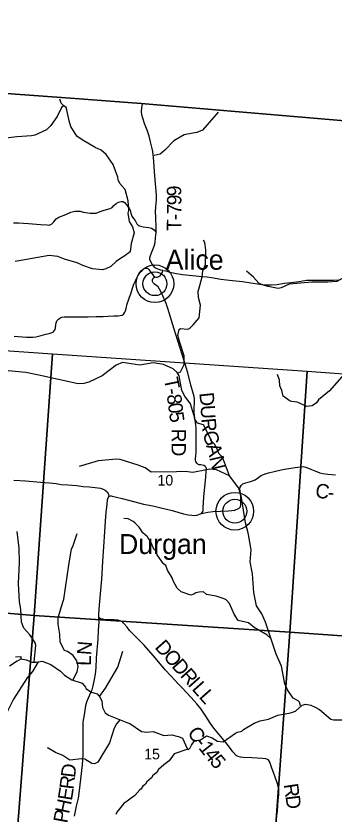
# Model space of a CAD drawing. Extents: x 1878108 to 2183446, y 146837 to 508383.
# Drawn here: x 2001746 to 2008379, y 360858 to 377520 of the extents above; entities that cross this region are included whole.
import ezdxf

# ---------------------------------------------------------------- set-up
doc = ezdxf.new("R2010")
doc.units = 0
for name, color, linetype in [('GM_X_Adjacent_County', 7, 'Continuous'), ('GM_X_County', 7, 'Continuous'), ('GM_X_County_Road', 7, 'Continuous'), ('GM_X_County_Road_Text', 7, 'Continuous'), ('GM_X_Minor_River', 7, 'Continuous'), ('GM_X_Section', 7, 'Continuous'), ('GM_X_Section_Text', 7, 'Continuous'), ('GM_X_Township', 7, 'Continuous'), ('GM_X_Township_Road', 7, 'Continuous'), ('GM_X_Township_Road_Text', 7, 'Continuous'), ('GM_X_Unincorporated', 7, 'Continuous'), ('GM_X_Unincorporated_Location', 7, 'Continuous'), ('GM_X_Unincorporated_Text', 7, 'Continuous')]:
    doc.layers.add(name, color=color, linetype=linetype)

msp = doc.modelspace()

# ---------------------------------------------------------------- linework, layer by layer
at = {"layer": 'GM_X_Adjacent_County'}
msp.add_lwpolyline([(2019246, 379371), (2019091, 377354), (2019015, 375973), (2018932, 374460), (2017235, 374591), (2014948, 374808), (2013541, 374918), (2012706, 374993), (2009261, 375273), (2004355, 375690), (2002882, 375803), (1999924, 376023), (1996643, 376255), (1995226, 376368), (1992658, 376556), (1989295, 376815), (1988220, 376891), (1986880, 376990), (1987114, 379254)], dxfattribs=at)
at = {"layer": 'GM_X_County'}
msp.add_lwpolyline([(1999924, 376023), (2002882, 375803), (2004355, 375690), (2009261, 375273), (2012706, 374993), (2013541, 374918), (2014948, 374808), (2017235, 374591), (2018932, 374460), (2018869, 373505), (2018611, 369652), (2018544, 369044), (2019394, 369075)], dxfattribs=at)
at = {"layer": 'GM_X_County_Road'}
for points in [[(2003832, 371261), (2003874, 371262), (2003918, 371265), (2003962, 371277), (2003992, 371304), (2004014, 371333), (2004028, 371364), (2004044, 371415), (2004068, 371512), (2004094, 371587), (2004114, 371650), (2004138, 371720), (2004175, 371834), (2004207, 371921), (2004243, 372007), (2004272, 372066), (2004290, 372097), (2004312, 372134), (2004337, 372171), (2004368, 372202), (2004396, 372230), (2004416, 372246), (2004440, 372256), (2004463, 372257), (2004484, 372253), (2004498, 372245), (2004515, 372227), (2004528, 372204), (2004551, 372179), (2004585, 372134), (2004614, 372098), (2004641, 372074), (2004672, 372065), (2004697, 372068), (2004724, 372078), (2004751, 372098), (2004802, 372170), (2004812, 372206), (2004869, 372196), (2004956, 372170), (2005091, 372143), (2005218, 372126), (2005430, 372099), (2005629, 372078), (2005735, 372071), (2005824, 372059), (2006017, 372028), (2006137, 372008), (2006259, 371995), (2006470, 371975), (2006642, 371952), (2006830, 371923), (2006955, 371910), (2007067, 371909), (2007193, 371917), (2007337, 371940), (2007476, 371958), (2007651, 371980), (2007802, 372001), (2007885, 372006), (2008006, 372006), (2008200, 372006), (2008362, 372007), (2008465, 372013)], [(2001710, 370832), (2001963, 370814), (2002097, 370812), (2002162, 370821), (2002268, 370848), (2002368, 370876), (2002438, 370890), (2002482, 370902), (2002519, 370922), (2002545, 370946), (2002561, 370976), (2002570, 371008), (2002575, 371075), (2002581, 371115), (2002599, 371154), (2002631, 371193), (2002672, 371219), (2002701, 371230), (2002753, 371238), (2002863, 371240), (2003005, 371240), (2003253, 371240), (2003419, 371245), (2003567, 371249), (2003671, 371254), (2003787, 371260), (2003832, 371261)], [(2003679, 367483), (2003693, 367496), (2003713, 367500), (2003734, 367501), (2003754, 367496), (2003845, 367474), (2003959, 367445), (2004222, 367376), (2004407, 367330), (2004598, 367293), (2004711, 367267), (2005001, 367198), (2005122, 367159), (2005240, 367126), (2005335, 367104), (2005415, 367095), (2005467, 367092), (2005518, 367100), (2005616, 367130), (2005749, 367164), (2005850, 367175), (2006013, 367182), (2006177, 367187), (2006247, 367197), (2006300, 367204), (2006361, 367220), (2006402, 367243), (2006426, 367275), (2006436, 367318), (2006435, 367395), (2006437, 367479), (2006430, 367542), (2006419, 367606), (2006416, 367643), (2006421, 367684), (2006440, 367719), (2006478, 367752), (2006537, 367775), (2006638, 367801), (2006682, 367813), (2006735, 367837), (2006812, 367892), (2006860, 367923), (2006945, 367963), (2007013, 367985), (2007130, 368009), (2007278, 368045), (2007344, 368060), (2007569, 368096), (2007682, 368110), (2007736, 368111), (2007793, 368100), (2007907, 368054), (2007979, 368023), (2008033, 368002), (2008081, 367981), (2008147, 367967), (2008251, 367955), (2008407, 367943)], [(2002964, 360813), (2003010, 361023), (2003047, 361189), (2003069, 361348), (2003100, 361587), (2003130, 361883), (2003147, 362092), (2003148, 362221), (2003147, 362411), (2003146, 362572), (2003150, 362778), (2003172, 362931), (2003201, 363124), (2003223, 363201), (2003256, 363282), (2003309, 363395), (2003332, 363452), (2003357, 363537), (2003386, 363668), (2003406, 363775), (2003418, 363908), (2003426, 364120), (2003457, 364510), (2003466, 364687), (2003479, 364871), (2003477, 364961), (2003473, 365032), (2003480, 365135), (2003511, 365453), (2003535, 365764), (2003560, 366131), (2003581, 366436), (2003597, 366754), (2003615, 366973), (2003630, 367156), (2003645, 367331), (2003656, 367420), (2003666, 367463), (2003679, 367483)], [(2003982, 364853), (2003966, 364869), (2003922, 364891), (2003871, 364905), (2003792, 364910), (2003682, 364911), (2003606, 364916), (2003550, 364925), (2003508, 364937), (2003477, 364961)], [(2007190, 360851), (2007205, 361022), (2007216, 361148), (2007225, 361259), (2007229, 361354), (2007224, 361404), (2007207, 361469), (2007139, 361667), (2007083, 361817), (2007040, 361938), (2007020, 361977), (2006993, 361999), (2006957, 362010), (2006888, 362018), (2006667, 362030), (2006486, 362038), (2006429, 362043), (2006379, 362059), (2006341, 362078), (2006272, 362155), (2006221, 362230), (2006126, 362352), (2005976, 362529), (2005874, 362652), (2005802, 362746), (2005706, 362900), (2005664, 362965), (2005606, 363051), (2005517, 363156), (2005398, 363290), (2005287, 363411), (2005223, 363476), (2005129, 363578), (2004976, 363747), (2004858, 363872), (2004659, 364114), (2004420, 364381), (2004311, 364494), (2004237, 364564), (2004152, 364650), (2004113, 364692), (2004063, 364758), (2004005, 364830), (2003982, 364853)]]:
    msp.add_lwpolyline(points, dxfattribs=at)
at = {"layer": 'GM_X_Minor_River'}
for points in [[(2002745, 375646), (2002687, 375699), (2002658, 375784)], [(2004015, 373906), (2003912, 374026), (2003876, 374096), (2003870, 374152), (2003774, 374418), (2003630, 374630), (2003520, 374718), (2003400, 374776), (2003124, 374932), (2003012, 375012), (2002892, 375216), (2002852, 375328), (2002807, 375562), (2002793, 375610), (2002745, 375646), (2002694, 375606), (2002608, 375424), (2002470, 375231), (2002382, 375143), (2002137, 375030), (2002073, 375016), (2001761, 374998), (2001250, 374931)], [(2005964, 375512), (2005635, 375137), (2005517, 375087), (2005437, 375074), (2005253, 375038), (2005040, 374915), (2004850, 374721), (2004750, 374635), (2004625, 374604)], [(2004015, 373907), (2004076, 373667), (2004092, 373462), (2004077, 373402), (2004108, 373229), (2004176, 373121), (2004211, 372990), (2004147, 372767), (2004129, 372598), (2003996, 372497)], [(2005117, 370065), (2005177, 370089), (2005251, 370245), (2005251, 370422), (2005165, 370700), (2005124, 370850), (2005148, 370976), (2005176, 370994), (2005320, 370980), (2005364, 370997), (2005444, 371075), (2005566, 371215), (2005595, 371480), (2005551, 371644), (2005549, 371774), (2005561, 371818), (2005630, 372075), (2005646, 372201), (2005696, 372333), (2005704, 372641), (2005686, 372788), (2005658, 372842)], [(2003997, 372497), (2003966, 372486), (2003832, 372396), (2003722, 372289), (2003618, 372239), (2003548, 372219), (2003341, 372239), (2003139, 372310), (2003021, 372368), (2002761, 372442), (2002621, 372498), (2002439, 372517), (2002204, 372481), (2001730, 372392)], [(2009454, 372110), (2009273, 372117), (2009093, 372079), (2008849, 372112), (2008729, 372124), (2008643, 372094), (2008436, 371978), (2008248, 371965), (2007916, 371963), (2007441, 371924), (2007279, 371847), (2007215, 371833), (2007003, 371869), (2006881, 371909), (2006809, 371945), (2006699, 372064), (2006551, 372190)], [(2009264, 370889), (2009168, 370627), (2009138, 370549), (2009043, 370450), (2008969, 370424), (2008899, 370430), (2008851, 370360), (2008775, 370304), (2008741, 370218), (2008288, 369692), (2008057, 369507), (2008011, 369445), (2007925, 369379), (2007811, 369367), (2007609, 369456), (2007499, 369468), (2007465, 369480), (2007320, 369580), (2007289, 369704), (2007247, 369798), (2007241, 369918), (2007201, 370035)], [(2003966, 370287), (2003832, 370233), (2003543, 370006), (2003263, 369875), (2003164, 369849), (2003046, 369843), (2002220, 370021), (2001953, 370079), (2001583, 370112)], [(2007681, 363116), (2007658, 363192), (2007634, 363220), (2007527, 363274), (2007410, 363450), (2007356, 363578), (2007286, 363946), (2007174, 364196), (2006947, 364861), (2006873, 365035), (2006763, 365203), (2006707, 365485), (2006676, 365876), (2006630, 366124), (2006654, 366372), (2006596, 366693), (2006584, 366757), (2006531, 366939), (2006447, 367470), (2006391, 367660), (2006201, 367922), (2006050, 368306), (2005976, 368384), (2005952, 368468), (2005886, 368582), (2005818, 368650), (2005790, 368726), (2005654, 368982), (2005532, 369016), (2005478, 369100), (2005462, 369180), (2005446, 369212), (2005386, 369422), (2005266, 369584), (2005208, 369704), (2005151, 370007), (2005109, 370079), (2005025, 370155), (2004825, 370246), (2004608, 370278), (2004332, 370232), (2003966, 370287)], [(2003917, 368262), (2003841, 368268), (2003459, 368233), (2003064, 368112)], [(2006201, 367922), (2005931, 368043), (2005787, 368057), (2005719, 368045), (2005437, 367990), (2005275, 368008), (2005094, 368006), (2004566, 367993), (2004440, 368089), (2004292, 368145), (2003917, 368262), (2003917, 368254)], [(2007065, 364517), (2006976, 364598), (2006714, 364750), (2006594, 364852), (2006382, 364900), (2006294, 365028), (2006202, 365254), (2006132, 365328), (2006086, 365348), (2005922, 365410), (2005720, 365441), (2005658, 365499), (2005564, 365487), (2005500, 365479), (2005456, 365447), (2005394, 365431), (2005194, 365494), (2005110, 365572), (2005024, 365728), (2005000, 365791), (2004906, 365953), (2004870, 366049), (2004824, 366079), (2004690, 366269), (2004656, 366361), (2004622, 366389), (2004554, 366553), (2004522, 366583), (2004492, 366647), (2004390, 366729), (2004312, 366845), (2004224, 366937), (2004192, 366963), (2004086, 367021), (2003992, 367030)], [(2002125, 364029), (2002159, 364383), (2002143, 364431), (2002111, 364487), (2002037, 364597), (2001907, 364741), (2001861, 364863), (2001848, 365134), (2001822, 365290), (2001796, 365669), (2001819, 366107), (2001811, 366418), (2001807, 366464), (2001773, 366760)], [(2002758, 364272), (2002669, 364448), (2002663, 364615), (2002624, 364823), (2002626, 364954), (2002687, 365171), (2002741, 365343), (2002845, 366057), (2002904, 366393), (2002931, 366445), (2003025, 366718)], [(2002932, 363651), (2003022, 363827), (2003045, 363939), (2003014, 364054), (2002939, 364165), (2002823, 364250), (2002758, 364272)], [(2003488, 363311), (2003613, 363489), (2003870, 363922), (2003969, 364238), (2003977, 364262)], [(2001739, 364142), (2001849, 364145), (2001847, 364095), (2001774, 364048), (2001611, 363945)], [(2001847, 364097), (2001961, 364079), (2002083, 364029), (2002165, 364029), (2002293, 364049), (2002473, 363983), (2002675, 363842), (2002757, 363758), (2002909, 363658), (2003129, 363594), (2003193, 363510), (2003203, 363482), (2003323, 363404), (2003437, 363368), (2003503, 363294), (2003537, 363216), (2003551, 363086), (2003605, 362972), (2003675, 362924), (2004059, 362769), (2004117, 362749), (2004361, 362583), (2004477, 362565), (2004604, 362583), (2004828, 362498), (2004998, 362510), (2005104, 362484), (2005132, 362480), (2005216, 362442), (2005316, 362224), (2005342, 362208), (2005380, 362240), (2005410, 362296), (2005468, 362389), (2005594, 362409), (2005721, 362489), (2005841, 362449), (2005891, 362415), (2005947, 362383), (2006069, 362366), (2006327, 362550), (2006369, 362566), (2006454, 362585), (2006490, 362621), (2006716, 362755), (2006838, 362806), (2007012, 362836), (2007207, 362925), (2007469, 362969), (2007577, 363009), (2007713, 363132), (2007794, 363152), (2007898, 363130), (2007988, 363088), (2008074, 363042), (2008310, 362842), (2008370, 362824), (2008570, 362827)], [(2002208, 364036), (2002093, 363835), (2001979, 363701), (2001697, 363258), (2001566, 363004), (2001404, 362757), (2001275, 362487), (2001185, 362342), (2001070, 362200), (2000888, 361993), (2000802, 361871), (2000566, 361649), (2000439, 361573), (2000273, 361545), (2000064, 361542), (1999936, 361545), (1999872, 361552), (1999567, 361683)], [(2003918, 362832), (2003843, 362743), (2003794, 362649), (2003697, 362343), (2003453, 361940), (2003382, 361906), (2003330, 361913), (2003183, 362002), (2003111, 362011), (2002868, 361985), (2002725, 362080), (2002571, 362140), (2002416, 362233), (2002404, 362239)], [(2005332, 362214), (2005048, 362117), (2004939, 361967), (2004833, 361889), (2004719, 361790), (2004683, 361724), (2004599, 361666), (2004570, 361616), (2004472, 361530), (2004446, 361483), (2004390, 361441), (2004358, 361381), (2004330, 361363), (2004224, 361243), (2003985, 361070), (2003851, 360894), (2003825, 360849)]]:
    msp.add_lwpolyline(points, dxfattribs=at)
at = {"layer": 'GM_X_Section'}
for points in [[(1997204, 370837), (2002510, 370465), (2002125, 365006), (1996800, 365454)], [(2002510, 370465), (2007822, 370107), (2007457, 364655), (2002125, 365006)], [(2013129, 369712), (2012803, 364282), (2007457, 364655), (2007822, 370107)], [(1996800, 365454), (2002125, 365006), (2001716, 359747), (1996427, 360078)], [(2002125, 365006), (2007457, 364655), (2007069, 359307), (2001716, 359747)], [(2012803, 364282), (2012417, 358952), (2007069, 359307), (2007457, 364655)]]:
    msp.add_lwpolyline(points, close=True, dxfattribs=at)
at = {"layer": 'GM_X_Township'}
msp.add_lwpolyline([(1999924, 376023), (2002882, 375803), (2004355, 375690), (2009261, 375273), (2012706, 374993), (2013541, 374918), (2014948, 374808), (2017235, 374591), (2018932, 374460), (2018869, 373505), (2018611, 369652), (2018544, 369044), (2018295, 364714), (2018284, 364566), (2017916, 358581), (2017697, 355615), (2017639, 354834), (2017363, 350985), (2017298, 350114), (2016876, 344501)], dxfattribs=at)
at = {"layer": 'GM_X_Township_Road'}
for points in [[(2004812, 372206), (2004765, 372216), (2004710, 372234), (2004657, 372252), (2004639, 372270), (2004586, 372341), (2004560, 372390), (2004538, 372438), (2004535, 372474), (2004551, 372517), (2004583, 372609), (2004626, 372716), (2004648, 372793), (2004657, 372885), (2004667, 373000), (2004672, 373088), (2004662, 373329), (2004657, 373431), (2004665, 373537), (2004678, 373673), (2004678, 373781), (2004644, 374182), (2004611, 374565), (2004597, 374690), (2004588, 374752), (2004554, 374895), (2004522, 375008), (2004482, 375136), (2004425, 375275), (2004390, 375390), (2004372, 375454), (2004363, 375529), (2004368, 375603), (2004386, 375688)], [(2001691, 373200), (2001797, 373199), (2002008, 373185), (2002260, 373167), (2002398, 373157), (2002440, 373156), (2002486, 373176), (2002532, 373221), (2002586, 373283), (2002640, 373317), (2002786, 373377), (2002893, 373423), (2002970, 373442), (2003040, 373447), (2003084, 373443), (2003150, 373424), (2003292, 373406), (2003354, 373400), (2003416, 373402), (2003501, 373439), (2003561, 373458), (2003633, 373477), (2003710, 373503), (2003749, 373521), (2003790, 373566), (2003833, 373608), (2003882, 373633), (2003939, 373647), (2003980, 373646), (2004010, 373624), (2004060, 373568), (2004106, 373508), (2004128, 373468), (2004141, 373403), (2004160, 373341), (2004197, 373292), (2004229, 373248), (2004267, 373179), (2004302, 373148), (2004341, 373131), (2004399, 373119), (2004462, 373111), (2004514, 373103), (2004574, 373087), (2004626, 373056), (2004667, 373000)], [(2005616, 367130), (2005644, 367175), (2005653, 367198), (2005649, 367249), (2005667, 367481), (2005681, 367610), (2005708, 367896), (2005715, 368012), (2005718, 368073), (2005711, 368096), (2005694, 368117), (2005661, 368134), (2005601, 368147), (2005569, 368152), (2005540, 368164), (2005517, 368184), (2005496, 368218), (2005488, 368243), (2005487, 368277), (2005495, 368334), (2005504, 368406), (2005506, 368489), (2005506, 368657), (2005507, 368827), (2005503, 368920), (2005493, 369035), (2005471, 369171), (2005462, 369256), (2005464, 369331), (2005471, 369448), (2005471, 369511), (2005464, 369574), (2005428, 369691), (2005391, 369809), (2005329, 370071), (2005222, 370432), (2005076, 370891), (2004916, 371410), (2004877, 371514), (2004789, 371725), (2004742, 371819), (2004711, 371863), (2004684, 371885), (2004637, 371921), (2004609, 371951), (2004594, 371977), (2004594, 372011), (2004606, 372043), (2004641, 372074)], [(2001698, 367832), (2001946, 367813), (2002257, 367787), (2002447, 367776), (2002587, 367759), (2002690, 367740), (2002828, 367729), (2003016, 367715), (2003149, 367700), (2003279, 367689), (2003453, 367668), (2003510, 367660), (2003565, 367643), (2003609, 367619), (2003646, 367585), (2003675, 367534), (2003679, 367483)]]:
    msp.add_lwpolyline(points, dxfattribs=at)
at = {"layer": 'GM_X_Unincorporated'}
for centre, radius in [((2004644, 371930), 393), ((2004644, 371930), 249), ((2006310, 367180), 393), ((2006310, 367180), 249)]:
    msp.add_circle(centre, radius, dxfattribs=at)
at = {"layer": 'GM_X_Unincorporated_Location'}
for p, q in [((2004644, 371930), (2004644, 371930)), ((2006310, 367180), (2006310, 367180))]:
    msp.add_line(p, q, dxfattribs=at)

# ---------------------------------------------------------------- texts
at = {"layer": 'GM_X_County_Road_Text'}
for s, rotation, p in [('C', 351.0256, (2007973, 367474)), ('-', 355.484, (2008242, 367432)), ('N', 85.6517, (2003312, 364169)), ('D', 311.6702, (2004627, 364331)), ('O', 311.6702, (2004803, 364134)), ('L', 88.562, (2003306, 363949)), ('D', 311.6702, (2004978, 363937)), ('R', 311.6698, (2005154, 363739)), ('I', 311.6698, (2005318, 363555)), ('L', 311.6693, (2005400, 363463)), ('L', 311.5068, (2005549, 363296)), ('C', 303.8703, (2005309, 362559)), ('-', 308.5791, (2005463, 362333)), ('1', 308.6141, (2005540, 362236)), ('4', 308.685, (2005655, 362091)), ('5', 309.4393, (2005773, 361944)), ('D', 83.2096, (2002977, 361606)), ('R', 83.0847, (2002947, 361361)), ('E', 80.9814, (2002911, 361127)), ('R', 278.5024, (2007328, 361475)), ('D', 277.3179, (2007365, 361233)), ('H', 77.8371, (2002852, 360851)), ('P', 79.6643, (2002816, 360655))]:
    msp.add_text(s, height=300, rotation=rotation, dxfattribs=at).set_placement(p)
at = {"layer": 'GM_X_Section_Text'}
for s, p in [('10', (2004696, 367717)), ('15', (2004419, 362000))]:
    msp.add_text(s, height=221, rotation=0, dxfattribs=at).set_placement(p)
at = {"layer": 'GM_X_Township_Road_Text'}
for s, rotation, p in [('9', 91.8269, (2005195, 373762)), ('9', 90.179, (2005196, 373568)), ('7', 89.5673, (2005194, 373379)), ('T', 89.3271, (2005190, 373030)), ('-', 89.3768, (2005193, 373255)), ('T', 281.8373, (2004826, 369943)), ('8', 277.2922, (2004890, 369608)), ('-', 278.9862, (2004871, 369728)), ('D', 276.0162, (2005568, 369648)), ('0', 277.0747, (2004914, 369425)), ('5', 278.2996, (2004937, 369235)), ('U', 272.9665, (2005595, 369390)), ('R', 275.5487, (2005610, 369112)), ('RD', 270, (2004990, 368905)), ('G', 283.4517, (2005641, 368822)), ('A', 285.842, (2005706, 368552)), ('N', 283.0988, (2005777, 368302))]:
    msp.add_text(s, height=300, rotation=rotation, dxfattribs=at).set_placement(p)
at = {"layer": 'GM_X_Unincorporated_Text'}
for s, p in [('Alice', (2004868, 372222)), ('Durgan', (2003895, 366287))]:
    msp.add_text(s, height=417, rotation=0, dxfattribs=at).set_placement(p)

doc.saveas('drawing.dxf')
